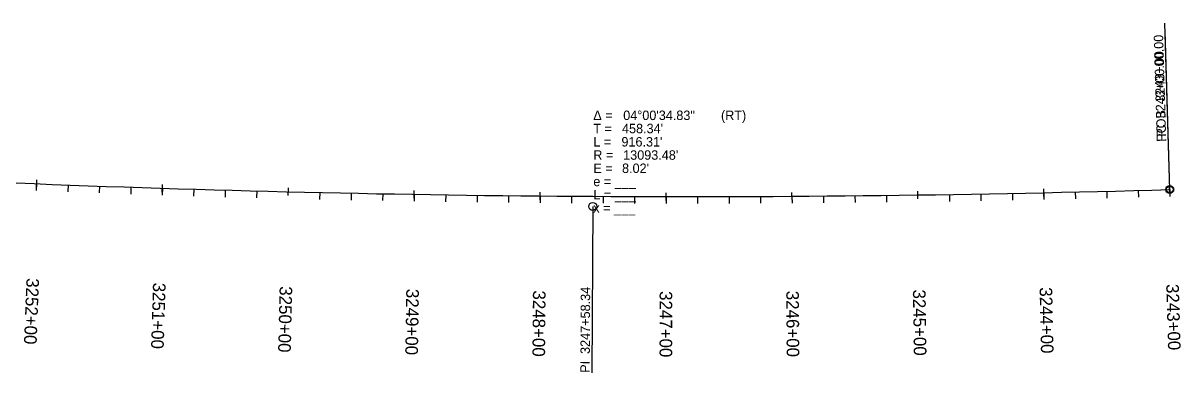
# Model space of a CAD drawing. Extents: x 15451313 to 15455081, y 8857737 to 8860760.
# Drawn here: x 15454162 to 15455081, y 8859026 to 8859303 of the extents above; entities that cross this region are included whole.
import ezdxf

# ---------------------------------------------------------------- set-up
doc = ezdxf.new("R2010")
doc.units = 0
for name, color, linetype in [('Annotation', 7, 'Continuous'), ('PC_REVISION_ANNOTATION', 7, 'Continuous'), ('SheetAddenda', 7, 'Continuous'), ('TextNonPlot', 7, 'Continuous')]:
    doc.layers.add(name, color=color, linetype=linetype)

msp = doc.modelspace()

# ---------------------------------------------------------------- linework, layer by layer
at = {"layer": 'Annotation'}
msp.add_arc((15454688.71, 8872259.4), 13093.48, 267.66912, 271.678795, dxfattribs=at)
at = {"layer": 'PC_REVISION_ANNOTATION'}
for p, q in [((15454172.37, 8859173.04), (15454172.61, 8859179.16)), ((15454197.47, 8859175.14), (15454197.27, 8859169.68)), ((15454222.45, 8859174.23), (15454222.26, 8859168.77)), ((15454272.33, 8859169.48), (15454272.52, 8859175.6)), ((15455072.39, 8859168.48), (15455072.21, 8859174.6)), ((15454247.44, 8859173.36), (15454247.26, 8859167.9)), ((15454297.41, 8859171.77), (15454297.25, 8859166.31)), ((15454322.4, 8859171.05), (15454322.25, 8859165.59)), ((15454347.39, 8859170.37), (15454347.25, 8859164.91)), ((15454372.31, 8859166.68), (15454372.46, 8859172.8)), ((15454397.38, 8859169.16), (15454397.26, 8859163.7)), ((15454422.37, 8859168.63), (15454422.26, 8859163.17)), ((15454447.37, 8859168.15), (15454447.27, 8859162.69)), ((15454472.32, 8859164.65), (15454472.42, 8859170.77)), ((15454497.36, 8859167.32), (15454497.28, 8859161.86)), ((15454522.36, 8859166.98), (15454522.29, 8859161.52)), ((15454547.36, 8859166.68), (15454547.3, 8859161.22)), ((15454572.33, 8859163.38), (15454572.38, 8859169.5)), ((15454597.36, 8859166.24), (15454597.32, 8859160.78)), ((15454622.36, 8859166.09), (15454622.33, 8859160.63)), ((15454647.36, 8859165.99), (15454647.34, 8859160.53)), ((15454672.35, 8859162.87), (15454672.36, 8859168.99)), ((15454697.36, 8859165.92), (15454697.36, 8859160.46)), ((15454722.36, 8859165.96), (15454722.37, 8859160.5)), ((15454747.36, 8859166.05), (15454747.38, 8859160.59)), ((15454772.37, 8859163.13), (15454772.34, 8859169.25)), ((15454797.35, 8859166.37), (15454797.4, 8859160.91)), ((15454822.35, 8859166.6), (15454822.41, 8859161.14)), ((15454847.35, 8859166.88), (15454847.42, 8859161.42)), ((15454872.39, 8859164.15), (15454872.31, 8859170.27)), ((15454897.35, 8859167.58), (15454897.43, 8859162.12)), ((15454922.34, 8859168.01), (15454922.44, 8859162.55)), ((15454947.34, 8859168.48), (15454947.45, 8859163.02)), ((15454972.4, 8859165.93), (15454972.27, 8859172.05)), ((15454997.33, 8859169.56), (15454997.46, 8859164.1)), ((15455022.32, 8859170.17), (15455022.46, 8859164.71)), ((15455047.31, 8859170.83), (15455047.46, 8859165.37))]:
    msp.add_line(p, q, dxfattribs=at)
at = {"layer": 'SheetAddenda'}
for p, q in [((15454172.49, 8859176.1), (15454172.27, 8859170.65)), ((15454272.43, 8859172.54), (15454272.25, 8859167.08)), ((15454372.31, 8859166.68), (15454372.46, 8859172.8)), ((15454472.37, 8859167.71), (15454472.28, 8859162.25)), ((15454572.36, 8859166.44), (15454572.31, 8859160.98)), ((15454672.36, 8859165.93), (15454672.35, 8859160.47)), ((15454772.36, 8859166.19), (15454772.39, 8859160.73)), ((15454872.39, 8859164.15), (15454872.31, 8859170.27)), ((15454972.33, 8859168.99), (15454972.45, 8859163.53)), ((15455072.3, 8859171.54), (15455072.46, 8859166.08))]:
    msp.add_line(p, q, dxfattribs=at)
at = {"layer": 'TextNonPlot'}
for p, q in [((15455072.3, 8859171.54), (15455068.43, 8859303.48)), ((15455068.43, 8859303.48), (15455068.43, 8859303.48)), ((15455072.3, 8859171.54), (15455068.61, 8859297.49)), ((15455068.61, 8859297.49), (15455068.61, 8859297.49)), ((15454614.16, 8859158.11), (15454613.41, 8859026.12)), ((15454613.41, 8859026.12), (15454613.41, 8859026.12))]:
    msp.add_line(p, q, dxfattribs=at)
for centre, radius in [((15455072.3, 8859171.54), 3.12), ((15455072.3, 8859171.54), 2.67), ((15454614.16, 8859158.11), 3.12)]:
    msp.add_circle(centre, radius, dxfattribs=at)

# ---------------------------------------------------------------- texts
at = {"layer": 'PC_REVISION_ANNOTATION'}
for s, rotation, p in [('3252+00', 267.74048, (15454164.53, 8859101.36)), ('3251+00', 268.17807, (15454265.03, 8859097.74)), ('3250+00', 268.61566, (15454365.57, 8859094.89)), ('3249+00', 269.05325, (15454466.12, 8859092.8)), ('3245+00', 270.80361, (15454868.39, 8859092.15)), ('3244+00', 271.2412, (15454968.95, 8859093.9)), ('3243+00', 271.6788, (15455069.49, 8859096.43)), ('3248+00', 269.49084, (15454566.68, 8859091.49)), ('3247+00', 269.92843, (15454667.25, 8859090.94)), ('3246+00', 270.36602, (15454767.82, 8859091.16))]:
    msp.add_text(s, height=10.02, rotation=rotation, dxfattribs=at).set_placement(p)
at = {"layer": 'SheetAddenda'}
for s, rotation, p in [('3250+00', 268.61566, (15454365.57, 8859094.89)), ('3245+00', 270.80361, (15454868.39, 8859092.15))]:
    msp.add_text(s, height=10.02, rotation=rotation, dxfattribs=at).set_placement(p)
at = {"layer": 'TextNonPlot'}
for s, rotation, p in [('3243+00.00', 91.6788, (15455068.61, 8859241.18)), ('3243+00.00', 91.6788, (15455069, 8859228.14)), ('POB ', 91.6788, (15455069.43, 8859213.48)), ('PC', 91.6788, (15455069.54, 8859209.48)), ('3247+58.34', 89.67396, (15454611.84, 8859041.07)), ('PI ', 89.67396, (15454611.76, 8859026.13))]:
    msp.add_text(s, height=7.5, rotation=rotation, dxfattribs=at).set_placement(p)
for s, p in [('Δ = ', (15454614.59, 8859226.65)), ('04°00\'34.83"', (15454638.34, 8859226.65)), (' (RT)', (15454713.19, 8859226.65)), ('T = ', (15454614.59, 8859216.15)), ("458.34'", (15454637.39, 8859216.15)), ('L = ', (15454614.59, 8859205.65)), ("916.31'", (15454636.93, 8859205.65)), ('R = ', (15454614.59, 8859195.15)), ("13093.48'", (15454638.29, 8859195.15)), ("8.02'", (15454637.41, 8859184.65)), ('E = ', (15454614.59, 8859184.65)), ('e = ___ ', (15454614.59, 8859174.15)), ('L = ___', (15454614.59, 8859163.65)), ('x = ___', (15454614.59, 8859153.15))]:
    msp.add_text(s, height=7.5, dxfattribs=at).set_placement(p)

doc.saveas('drawing.dxf')
